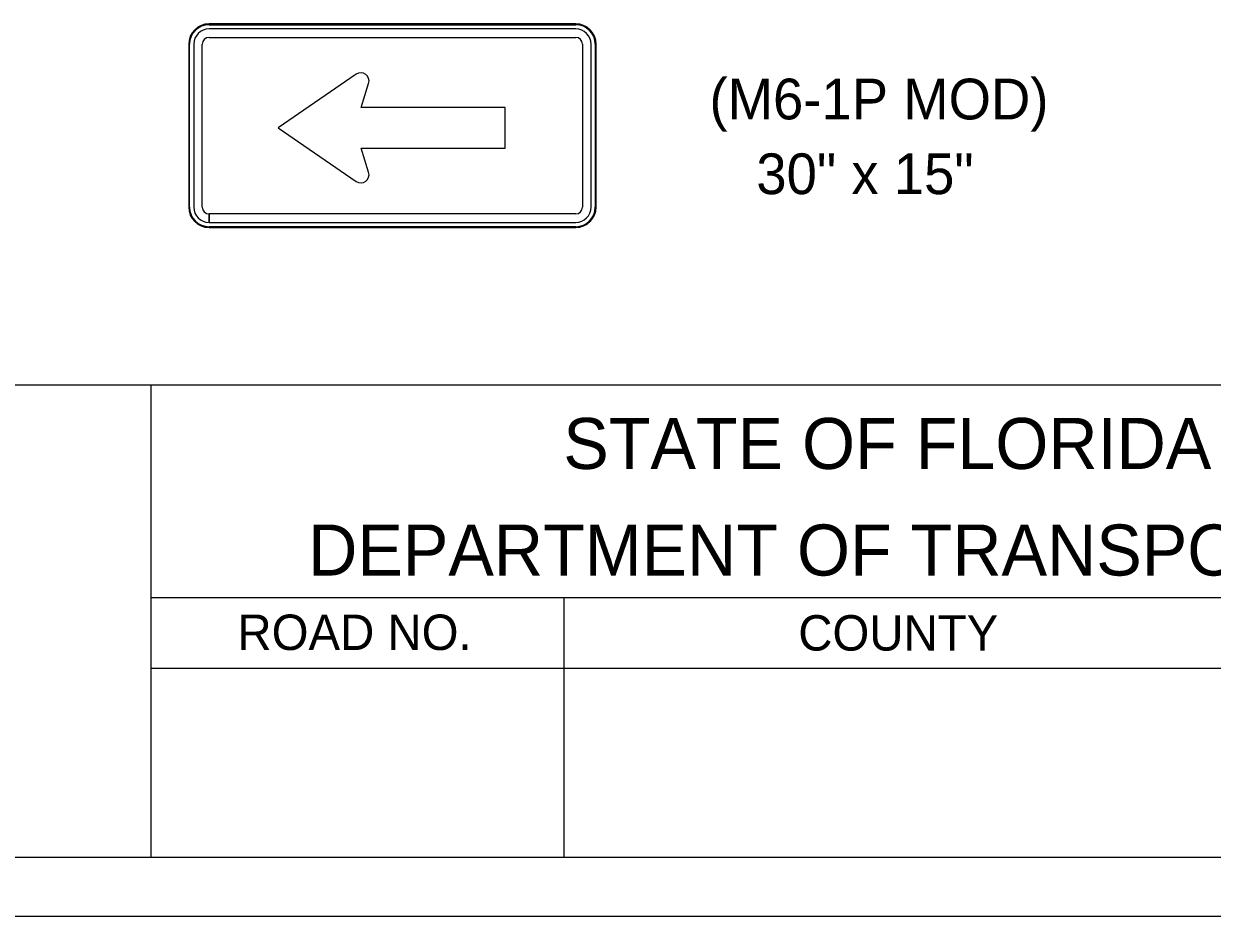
# Model space of a CAD drawing. Extents: x 17890587 to 17890754, y 17897693 to 17897992.
# Drawn here: x 17890611.5 to 17890617.41, y 17897873.1 to 17897877.54 of the extents above; entities that cross this region are included whole.
import ezdxf

# ---------------------------------------------------------------- set-up
doc = ezdxf.new("R2010")
doc.units = 0
for name, color, linetype in [('GSBWFill', 7, 'Continuous'), ('GSColorFill', 7, 'Continuous'), ('GSOutline', 7, 'Continuous'), ('PlotBorder_dp', 7, 'Continuous'), ('SheetBorder_dp', 7, 'Continuous'), ('SheetLines_dp', 7, 'Continuous'), ('TextMisc', 7, 'Continuous')]:
    doc.layers.add(name, color=color, linetype=linetype)

msp = doc.modelspace()

# ---------------------------------------------------------------- linework, layer by layer
at = {"layer": 'GSBWFill'}
for points in [[(17890613.1559, 17897877.2887), (17890612.7678, 17897877.0225), (17890613.1559, 17897876.7562)], [(17890613.2174, 17897876.8019), (17890613.1795, 17897876.9213), (17890613.8958, 17897876.9213), (17890613.8958, 17897877.1237), (17890613.1795, 17897877.1237), (17890613.2174, 17897877.2431)]]:
    msp.add_lwpolyline(points, dxfattribs=at)
for centre, major_axis, start_param, end_param in [((17890613.1788, 17897877.2553), (0.0405, 0), 5.975991, 8.455234), ((17890613.1788, 17897876.7896), (-0.0405, 0), 0.969544, 3.448787)]:
    msp.add_ellipse(centre, major_axis=major_axis, ratio=0.999949, start_param=start_param, end_param=end_param, dxfattribs=at)
at = {"layer": 'GSColorFill'}
for p, q in [((17890614.2466, 17897877.5392), (17890612.4243, 17897877.5392)), ((17890614.2466, 17897877.5392), (17890612.4243, 17897877.5392)), ((17890612.4243, 17897877.535), (17890614.2466, 17897877.535)), ((17890614.2466, 17897877.5139), (17890612.4243, 17897877.5139)), ((17890612.4243, 17897877.4717), (17890614.2466, 17897877.4717)), ((17890612.323, 17897877.4379), (17890612.323, 17897876.628)), ((17890612.323, 17897877.4379), (17890612.323, 17897876.628)), ((17890612.3273, 17897876.628), (17890612.3273, 17897877.4379)), ((17890612.3483, 17897877.4379), (17890612.3483, 17897876.628)), ((17890612.3905, 17897876.628), (17890612.3905, 17897877.4379)), ((17890614.2803, 17897877.4379), (17890614.2803, 17897876.628)), ((17890614.3225, 17897876.628), (17890614.3225, 17897877.4379)), ((17890614.3436, 17897877.4379), (17890614.3436, 17897876.628)), ((17890614.3478, 17897876.628), (17890614.3478, 17897877.4379)), ((17890614.3478, 17897876.628), (17890614.3478, 17897877.4379)), ((17890612.4243, 17897876.5521), (17890612.4243, 17897876.5943)), ((17890614.2466, 17897876.5943), (17890612.4247, 17897876.5943)), ((17890612.4247, 17897876.5943), (17890612.4247, 17897876.5521)), ((17890612.4243, 17897876.5268), (17890612.4243, 17897876.531)), ((17890614.2466, 17897876.531), (17890612.4243, 17897876.531)), ((17890612.4243, 17897876.531), (17890612.4243, 17897876.5268)), ((17890612.4243, 17897876.5268), (17890614.2466, 17897876.5268)), ((17890612.4243, 17897876.5268), (17890614.2466, 17897876.5268)), ((17890612.4247, 17897876.5521), (17890614.2466, 17897876.5521))]:
    msp.add_line(p, q, dxfattribs=at)
for points in [[(17890613.1559, 17897877.2887), (17890612.7678, 17897877.0225), (17890613.1559, 17897876.7562)], [(17890613.2174, 17897876.8019), (17890613.1795, 17897876.9213), (17890613.8958, 17897876.9213), (17890613.8958, 17897877.1237), (17890613.1795, 17897877.1237), (17890613.2174, 17897877.2431)]]:
    msp.add_lwpolyline(points, dxfattribs=at)
for centre, radius, start, end in [((17890612.4243, 17897877.4379), 0.1012, 90, 180), ((17890612.4243, 17897877.4379), 0.1012, 90, 180), ((17890612.4243, 17897877.4379), 0.097, 90, 180), ((17890612.4243, 17897877.4379), 0.0759, 90, 180), ((17890614.2466, 17897877.4379), 0.1012, 0, 90), ((17890614.2466, 17897877.4379), 0.1012, 0, 90), ((17890614.2466, 17897877.4379), 0.097, 0, 90), ((17890614.2466, 17897877.4379), 0.0759, 0, 90), ((17890612.4243, 17897877.4379), 0.0337, 90, 180), ((17890614.2466, 17897877.4379), 0.0337, 0, 90), ((17890612.4243, 17897876.628), 0.1012, 180, 270), ((17890612.4243, 17897876.628), 0.1012, 180, 270), ((17890612.4243, 17897876.628), 0.097, 180, 270), ((17890612.4243, 17897876.628), 0.0759, 180, 270), ((17890612.4243, 17897876.628), 0.0337, 180, 270), ((17890614.2466, 17897876.628), 0.1012, 270, 0), ((17890614.2466, 17897876.628), 0.1012, 270, 0), ((17890614.2466, 17897876.628), 0.097, 270, 0), ((17890614.2466, 17897876.628), 0.0759, 270, 0), ((17890614.2466, 17897876.628), 0.0337, 270, 0)]:
    msp.add_arc(centre, radius, start, end, dxfattribs=at)
for centre, major_axis, start_param, end_param in [((17890613.1788, 17897877.2553), (0.0405, 0), 5.975991, 8.455234), ((17890613.1788, 17897876.7896), (-0.0405, 0), 0.969544, 3.448787)]:
    msp.add_ellipse(centre, major_axis=major_axis, ratio=0.999949, start_param=start_param, end_param=end_param, dxfattribs=at)
at = {"layer": 'GSOutline'}
for points in [[(17890613.1559, 17897877.2887), (17890612.7678, 17897877.0225), (17890613.1559, 17897876.7562)], [(17890613.2174, 17897876.8019), (17890613.1795, 17897876.9213), (17890613.8958, 17897876.9213), (17890613.8958, 17897877.1237), (17890613.1795, 17897877.1237), (17890613.2174, 17897877.2431)]]:
    msp.add_lwpolyline(points, dxfattribs=at)
for centre, major_axis, start_param, end_param in [((17890613.1788, 17897877.2553), (0.0405, 0), 5.975991, 8.455234), ((17890613.1788, 17897876.7896), (-0.0405, 0), 0.969544, 3.448787)]:
    msp.add_ellipse(centre, major_axis=major_axis, ratio=0.999949, start_param=start_param, end_param=end_param, dxfattribs=at)
at = {"layer": 'PlotBorder_dp'}
msp.add_lwpolyline([(17890586.7562, 17897873.1039), (17890635.165, 17897873.1039), (17890635.165, 17897904.2029), (17890586.7562, 17897904.2029)], close=True, dxfattribs=at)
at = {"layer": 'SheetBorder_dp'}
for p, q in [((17890588.3699, 17897875.7444), (17890633.5514, 17897875.7444)), ((17890588.3699, 17897873.3973), (17890633.5514, 17897873.3973))]:
    msp.add_line(p, q, dxfattribs=at)
at = {"layer": 'SheetLines_dp'}
for p, q in [((17890612.1342, 17897875.7444), (17890612.1342, 17897873.3973)), ((17890612.1342, 17897874.6882), (17890620.9358, 17897874.6882)), ((17890614.1879, 17897874.6882), (17890614.1879, 17897873.3973)), ((17890612.1342, 17897874.3361), (17890620.9358, 17897874.3361))]:
    msp.add_line(p, q, dxfattribs=at)

# ---------------------------------------------------------------- texts
at = {"layer": 'TextMisc'}
for s, height, p in [('(M6-1P MOD)', 0.202479, (17890614.9113, 17897877.0642)), ('30" x 15"', 0.20248, (17890615.1439, 17897876.6927)), ('STATE OF FLORIDA', 0.253486, (17890614.1847, 17897875.3269)), ('DEPARTMENT OF TRANSPORTATION', 0.253486, (17890612.9166, 17897874.7972)), ('ROAD NO.', 0.17603, (17890612.5654, 17897874.4271)), ('COUNTY', 0.17603, (17890615.3526, 17897874.4242))]:
    msp.add_text(s, height=height, dxfattribs=at).set_placement(p)

doc.saveas('drawing.dxf')
